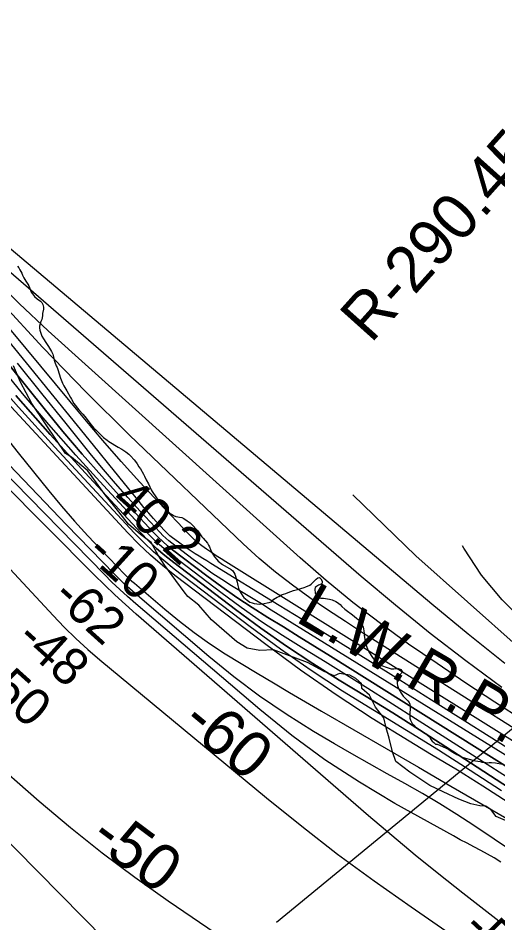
# Model space of a CAD drawing. Extents: x 3192986 to 3230865, y 867483 to 892886.
# Drawn here: x 3218620 to 3219484, y 874998 to 876628 of the extents above; entities that cross this region are included whole.
import ezdxf

# ---------------------------------------------------------------- set-up
doc = ezdxf.new("R2010")
doc.units = 0
for name, color, linetype in [('V-RIVR-EDGE', 7, 'Continuous'), ('V-RIVR-RANG', 7, 'Continuous'), ('V-RIVR-RANG-IDEN', 7, 'Continuous'), ('V-SITE-VEGE', 7, 'Continuous'), ('V-TOPO-DPTH', 7, 'Continuous'), ('V-TOPO-MAJR', 7, 'Continuous'), ('V-TOPO-MAJR-IDEN', 7, 'Continuous'), ('V-TOPO-MINR', 7, 'Continuous'), ('V-TOPO-MINR-IDEN', 7, 'Continuous'), ('V-TOPO-WATR', 7, 'Continuous'), ('V-TOPO-WATR-IDEN', 7, 'Continuous')]:
    doc.layers.add(name, color=color, linetype=linetype)

msp = doc.modelspace()

# ---------------------------------------------------------------- linework, layer by layer
at = {"layer": 'V-RIVR-EDGE'}
msp.add_lwpolyline([(3219498, 875182.3), (3219481.1, 875189.7), (3219471.6, 875202.3), (3219462.5, 875208), (3219451.6, 875208.5), (3219435.1, 875212), (3219413.8, 875220.7), (3219385.6, 875233.8), (3219361.3, 875245.2), (3219325.3, 875269.6), (3219300.5, 875288.4), (3219294.5, 875306.2), (3219288, 875330.6), (3219282.9, 875349.3), (3219278.5, 875367.1), (3219263.4, 875386.7), (3219252.6, 875408), (3219239.1, 875420.2), (3219238.7, 875428.9), (3219228.3, 875438.1), (3219217.4, 875443.8), (3219198.8, 875446.8), (3219189.2, 875443), (3219171, 875450.8), (3219141, 875467), (3219104.1, 875480.6), (3219080.2, 875489.7), (3219055.4, 875488.5), (3219032.8, 875492.9), (3219013.7, 875504.2), (3218968.6, 875543.9), (3218945.7, 875570.1), (3218925.7, 875585.7), (3218918.8, 875594.5), (3218904, 875614.5), (3218884.5, 875641.5), (3218872.4, 875660.2), (3218859.9, 875682.8), (3218840.3, 875697.7), (3218818.7, 875716), (3218801.3, 875738.2), (3218776.6, 875768.7), (3218745.9, 875812.2), (3218715.9, 875836.6), (3218705.1, 875843.2), (3218670.4, 875895), (3218644.9, 875933.3), (3218624.1, 875972.1), (3218612, 876001.6)], dxfattribs=at)
at = {"layer": 'V-RIVR-RANG'}
msp.add_line((3219857.7, 875633.4), (3219085.2, 874998.4), dxfattribs=at)
at = {"layer": 'V-SITE-VEGE'}
for points in [[(3218618.8, 876180.8), (3218621.2, 876177.8), (3218623.3, 876174.5), (3218626.6, 876168.1)], [(3218626.6, 876168.1), (3218628, 876164.6), (3218630.4, 876160.1), (3218634.1, 876153.8), (3218637.7, 876148.7), (3218639.3, 876145.2), (3218642.1, 876137.6), (3218643.7, 876134.3), (3218645.7, 876131.3), (3218649.8, 876126.4), (3218654.6, 876122), (3218660.5, 876117.9), (3218662.6, 876115.4), (3218664.5, 876112), (3218666, 876107.2), (3218665.6, 876103.6), (3218664, 876095.4), (3218663.7, 876091.7), (3218662.6, 876084.9), (3218661.1, 876081.2), (3218659.8, 876077.1), (3218658.8, 876073), (3218658.5, 876069.6), (3218659, 876065.8), (3218661.4, 876058.7), (3218663, 876055), (3218665.9, 876049.9), (3218669.9, 876043.5), (3218675, 876036.1), (3218680.2, 876027.4), (3218682.3, 876022.4), (3218683.6, 876017.8), (3218684.9, 876011.7), (3218685.9, 876008.1), (3218688.7, 876001.4), (3218690.4, 875998.6), (3218691.7, 875995), (3218693.9, 875987.1), (3218696.5, 875979.4), (3218700.1, 875970), (3218702.2, 875965.4), (3218707.9, 875956.1), (3218714.5, 875944.3), (3218715.9, 875941.4), (3218720.3, 875933.5), (3218722.5, 875930.5), (3218727, 875925.2), (3218729.5, 875922), (3218736.8, 875914.1), (3218740, 875910.3), (3218751.4, 875894.9), (3218756.7, 875889), (3218759.8, 875885.8), (3218773.7, 875872.4), (3218780.3, 875867.5), (3218783.6, 875865.3), (3218800.5, 875854.6), (3218806.7, 875851), (3218813.9, 875846.2), (3218819.4, 875842), (3218822.7, 875839), (3218829.1, 875831.9), (3218831.5, 875828.9), (3218834.3, 875824.8), (3218837.6, 875819.2), (3218840.2, 875815.5), (3218845.6, 875806.1), (3218847.9, 875802.7), (3218850.9, 875796.2), (3218854.6, 875788.5), (3218859.7, 875778.2), (3218861.5, 875775), (3218869.4, 875763.3), (3218878, 875751.8), (3218888.4, 875740.6), (3218893.7, 875735.6), (3218897.2, 875733.3), (3218899.9, 875731.7), (3218903.8, 875730.1), (3218907.7, 875729.2), (3218910.8, 875728.9), (3218914.9, 875727.9), (3218918.3, 875726.3), (3218924.7, 875722.2), (3218929.7, 875718.4), (3218932.2, 875716.3), (3218935.5, 875713.3), (3218940.1, 875707.9), (3218943.4, 875703.8), (3218951.1, 875693.4), (3218953.3, 875691), (3218961.1, 875681.7), (3218963.1, 875678.5), (3218964.9, 875675.3), (3218966.6, 875670.7), (3218969.7, 875663.8), (3218971.8, 875660.2), (3218974, 875657), (3218977.8, 875652.3), (3218980.5, 875649.4), (3218988, 875643.5)], [(3218988, 875643.5), (3219003.5, 875634.4), (3219006.5, 875632), (3219008.7, 875629.3), (3219010.5, 875626), (3219011.7, 875622.7), (3219014.5, 875611.5), (3219015.7, 875605.4), (3219016.8, 875600.6), (3219018.5, 875596.2), (3219021.9, 875591.1), (3219024.7, 875586.6), (3219026.6, 875584.1), (3219032.5, 875579), (3219037.6, 875575.6), (3219041.6, 875574.1), (3219045, 875573.2), (3219049.8, 875572.3), (3219055, 875572.2), (3219063.3, 875573.2), (3219068.8, 875574.3), (3219072.4, 875574.7), (3219075.5, 875575.9), (3219078.4, 875577.9), (3219080.8, 875580.8), (3219083.3, 875583), (3219086.6, 875584.6), (3219089.5, 875585.9), (3219094.3, 875588.6), (3219098.1, 875590.2), (3219102.1, 875591.3), (3219106.1, 875593.1), (3219116.1, 875596.9), (3219123, 875598.7), (3219135.3, 875602.1), (3219138.4, 875603.2), (3219145.2, 875606.3), (3219147.9, 875608.2), (3219150.4, 875610.3), (3219156.6, 875616.9), (3219159.6, 875619.4), (3219162.7, 875619.8), (3219165, 875617.6), (3219167.4, 875613.4), (3219167.8, 875609.9), (3219165.6, 875607.9), (3219161.2, 875606), (3219157.2, 875604), (3219154.7, 875602.3), (3219154.1, 875598.8), (3219154.8, 875591.5), (3219156.6, 875587.9), (3219158.8, 875585.5), (3219161.3, 875584), (3219165, 875583), (3219169.8, 875582.5), (3219177.4, 875581.5), (3219181, 875580.7), (3219185.6, 875579.5), (3219192.1, 875576.7), (3219195.1, 875575), (3219197.6, 875573.2), (3219199.9, 875571.1), (3219202.9, 875567.9), (3219208.2, 875563.2), (3219210.9, 875561), (3219222.5, 875552.5), (3219229.4, 875547), (3219232.5, 875544.4), (3219235.1, 875541.8), (3219237.4, 875538.7), (3219240.2, 875533.8), (3219241.4, 875530.6), (3219242.3, 875527.7), (3219242.8, 875524.1), (3219243, 875519.3), (3219243.3, 875516.1), (3219243.9, 875511.7), (3219245.4, 875503.2), (3219246.1, 875500.3), (3219247.4, 875496.3), (3219249.8, 875490), (3219251.7, 875486.1), (3219258.3, 875476.1), (3219262.3, 875470.6), (3219264.6, 875468), (3219268.6, 875465.1), (3219271.5, 875463.2), (3219274.2, 875461.7), (3219277.9, 875460.1), (3219281, 875459.2), (3219288.5, 875456.4), (3219292.1, 875455.6), (3219296.5, 875455.5), (3219304.8, 875456.1), (3219309.5, 875454.1), (3219311.7, 875450.5), (3219310.3, 875447.8), (3219308.2, 875445), (3219305.4, 875441.4), (3219303.4, 875437.4)], [(3219303.4, 875437.4), (3219302.7, 875433.9), (3219302.4, 875429.1), (3219303.2, 875425.2), (3219305.1, 875420.1), (3219307.2, 875416), (3219308.8, 875413.3), (3219313.7, 875406.2), (3219316.5, 875403.2), (3219322.1, 875397.8), (3219324, 875395.1), (3219325.6, 875391.6), (3219325.8, 875388.2), (3219325.8, 875383.7), (3219325.3, 875375.9), (3219325.2, 875366.7), (3219326.4, 875363), (3219328.2, 875359.5), (3219329.9, 875356.9), (3219332.5, 875353.7), (3219335.7, 875350.6), (3219353.9, 875338.9), (3219356.9, 875336.5), (3219360, 875333.6), (3219362, 875331.1), (3219363.4, 875328.1), (3219365.9, 875325.2), (3219368.5, 875322.6), (3219371.7, 875319.8), (3219374.8, 875319.6), (3219389.9, 875313.4), (3219396, 875309.9), (3219399.9, 875307.4), (3219402.9, 875305.2), (3219409.9, 875301.2), (3219416.7, 875297.9), (3219420, 875296.6), (3219432.4, 875292.7), (3219439.2, 875290.9), (3219443.9, 875289.7), (3219448, 875288.9), (3219452, 875288.4), (3219455.4, 875287.6), (3219459, 875287.1), (3219462.1, 875286.5), (3219465.3, 875286.2), (3219468.5, 875286.7), (3219472.8, 875287), (3219480, 875286.1), (3219492.1, 875283.9)]]:
    msp.add_lwpolyline(points, dxfattribs=at)
at = {"layer": 'V-TOPO-DPTH'}
for points in [[(3219692, 875192.4), (3219364.3, 875399.1), (3219296, 875442), (3219227.5, 875484.8), (3219159, 875527.3), (3219090.4, 875569.7), (3218967.2, 875645.4), (3218960, 875649.8), (3218952.9, 875654.2), (3218945.8, 875658.6), (3218938.6, 875662.9), (3218931.5, 875667.4), (3218924.6, 875672), (3218917.7, 875676.8), (3218911, 875681.8), (3218895.7, 875693.4), (3218893.5, 875695.2), (3218891.4, 875697), (3218889.3, 875699), (3218887.3, 875701), (3218873.1, 875716.4), (3218864.1, 875726.3), (3218855.3, 875736.2), (3218846.7, 875746.4), (3218838.2, 875756.7), (3218819.3, 875780), (3218801.5, 875802), (3218783.6, 875824), (3218765.8, 875846), (3218747.9, 875868), (3218395.4, 876300.2)], [(3218519.2, 876107.9), (3218666.7, 875924.7), (3218700.8, 875883.3), (3218735.4, 875842.4), (3218770.8, 875802.3), (3218806.8, 875762.6), (3218864.1, 875700.8), (3218872.1, 875692.7), (3218880.4, 875684.8), (3218889, 875677.3), (3218897.9, 875670.1), (3218960, 875622.9), (3218986.8, 875603.3), (3219013.9, 875584.1), (3219041.6, 875565.9), (3219069.7, 875548.2), (3219098.1, 875530.9), (3219126.4, 875513.4), (3219154.6, 875495.9), (3219182.8, 875478.3), (3219639.8, 875191)], [(3218519.2, 876107.9), (3218666.7, 875924.7), (3218700.8, 875883.3), (3218735.4, 875842.4), (3218770.8, 875802.3), (3218806.8, 875762.6), (3218864.1, 875700.8), (3218872.1, 875692.7), (3218880.4, 875684.8), (3218889, 875677.3), (3218897.9, 875670.1), (3218960, 875622.9), (3218986.8, 875603.3), (3219013.9, 875584.1), (3219041.6, 875565.9), (3219069.7, 875548.2), (3219098.1, 875530.9), (3219126.4, 875513.4), (3219154.6, 875495.9), (3219182.8, 875478.3), (3219639.8, 875191)], [(3218615.7, 875947.8), (3218677.9, 875877.8), (3218740.9, 875808.6), (3218840.9, 875700.7), (3218854.9, 875686.3), (3218869.4, 875672.5), (3218884.5, 875659.4), (3218900.2, 875646.9), (3219011.4, 875562.3), (3219057, 875528.8), (3219103.2, 875496.3), (3219150.6, 875465.3), (3219198.5, 875435.3), (3219246.9, 875405.8), (3219295, 875376), (3219342.9, 875345.7), (3219390.5, 875315.1), (3219618, 875167.4)], [(3219618, 875167.4), (3219390.5, 875315.1), (3219342.9, 875345.7), (3219295, 875376), (3219246.9, 875405.8), (3219198.5, 875435.3), (3219150.6, 875465.3), (3219103.2, 875496.3), (3219057, 875528.8), (3219011.4, 875562.3), (3218900.2, 875646.9), (3218884.5, 875659.4), (3218869.4, 875672.5), (3218854.9, 875686.3), (3218840.9, 875700.7), (3218740.9, 875808.6), (3218677.9, 875877.8), (3218615.7, 875947.8)], [(3219502.8, 875214.5), (3219457.2, 875244), (3219411.1, 875272.7), (3219364.7, 875300.8), (3219324.1, 875325), (3219257.8, 875366), (3219192.6, 875408.5), (3219128.8, 875453.1), (3219066, 875499.2), (3218902.4, 875623.6), (3218880, 875641.5), (3218858.4, 875660.2), (3218837.7, 875680), (3218817.7, 875700.5), (3218599.5, 875936)], [(3219502.8, 875214.5), (3219457.2, 875244), (3219411.1, 875272.7), (3219364.7, 875300.8), (3219324.1, 875325), (3219257.8, 875366), (3219192.6, 875408.5), (3219128.8, 875453.1), (3219066, 875499.2), (3218902.4, 875623.6), (3218880, 875641.5), (3218858.4, 875660.2), (3218837.7, 875680), (3218817.7, 875700.5), (3218599.5, 875936)], [(3218579.3, 875895.9), (3218620.3, 875844.9), (3218675.5, 875776.3), (3218698.3, 875748.7), (3218721.6, 875721.6), (3218745.7, 875695.1), (3218770.2, 875669), (3218811.6, 875626.3), (3218815.9, 875622), (3218820.3, 875617.8), (3218824.8, 875613.7), (3218829.4, 875609.6), (3218884.3, 875562.7), (3218910.4, 875541.4), (3218937.2, 875520.8), (3218964.8, 875501.4), (3218993, 875482.8), (3219021.8, 875465), (3219050.7, 875447.4), (3219079.7, 875430.1), (3219108.9, 875412.9), (3219166.6, 875379.3), (3219224.8, 875345.6), (3219282.9, 875311.8), (3219341.1, 875278.1), (3219399.2, 875244.3), (3219601.2, 875127.3)], [(3218579.3, 875895.9), (3218620.3, 875844.9), (3218675.5, 875776.3), (3218698.3, 875748.7), (3218721.6, 875721.6), (3218745.7, 875695.1), (3218770.2, 875669), (3218811.6, 875626.3), (3218815.9, 875622), (3218820.3, 875617.8), (3218824.8, 875613.7), (3218829.4, 875609.6), (3218884.3, 875562.7), (3218910.4, 875541.4), (3218937.2, 875520.8), (3218964.8, 875501.4), (3218993, 875482.8), (3219021.8, 875465), (3219050.7, 875447.4), (3219079.7, 875430.1), (3219108.9, 875412.9), (3219166.6, 875379.3), (3219224.8, 875345.6), (3219282.9, 875311.8), (3219341.1, 875278.1), (3219399.2, 875244.3), (3219601.2, 875127.3)], [(3219548.9, 875100.3), (3219440.7, 875173.3), (3219410.2, 875193.2), (3219379.4, 875212.5), (3219348, 875230.9), (3219316.3, 875248.8), (3219284.4, 875266.3), (3219252.6, 875284.1), (3219221, 875302.3), (3219189.6, 875320.6), (3219152.1, 875342.8), (3219102.9, 875373.7), (3219054.9, 875406.1), (3219008.6, 875441.1), (3218963.5, 875477.6), (3218830.6, 875591.2), (3218821.1, 875599.6), (3218811.7, 875608.2), (3218802.6, 875617), (3218793.6, 875626), (3218707.3, 875715.1), (3218655.5, 875768.9), (3218603.9, 875823)], [(3219548.9, 875100.3), (3219440.7, 875173.3), (3219410.2, 875193.2), (3219379.4, 875212.5), (3219348, 875230.9), (3219316.3, 875248.8), (3219284.4, 875266.3), (3219252.6, 875284.1), (3219221, 875302.3), (3219189.6, 875320.6), (3219152.1, 875342.8), (3219102.9, 875373.7), (3219054.9, 875406.1), (3219008.6, 875441.1), (3218963.5, 875477.6), (3218830.6, 875591.2), (3218821.1, 875599.6), (3218811.7, 875608.2), (3218802.6, 875617), (3218793.6, 875626), (3218707.3, 875715.1), (3218655.5, 875768.9), (3218603.9, 875823)], [(3218494.5, 875253), (3219097.1, 874642)], [(3218494.5, 875253), (3219097.1, 874642)]]:
    msp.add_lwpolyline(points, dxfattribs=at)
at = {"layer": 'V-TOPO-MAJR'}
for points in [[(3219530.7, 875361.7), (3219478.3, 875395.6), (3219426.2, 875429.9), (3219374.5, 875464.9), (3219323.1, 875500.2), (3219272.6, 875536.9), (3219223.1, 875574.7), (3219175.1, 875614.4), (3219128, 875655.3), (3218674.1, 876064.7), (3218621.8, 876113.6), (3218570.7, 876163.8), (3218521.5, 876215.8), (3218473.6, 876269), (3218398, 876356.1), (3218388.9, 876366.8), (3218380, 876377.5), (3218371.3, 876388.5), (3218362.7, 876399.6), (3217944.5, 877172.1)], [(3219489.1, 875107.4), (3219477.5, 875114.9), (3219465.5, 875121.8), (3219453.3, 875128.4), (3219440.9, 875134.7), (3219428.7, 875141.1), (3219416.4, 875147.7), (3219404.3, 875154.4), (3219298.4, 875213.1), (3219234.6, 875251.1), (3219172.5, 875291.5), (3219113, 875335.5), (3219055.2, 875382), (3218831.8, 875572.8), (3218817.3, 875585.5), (3218803.1, 875598.5), (3218789.1, 875611.9), (3218775.4, 875625.5), (3218586.8, 875818)], [(3218563, 875300), (3218658.1, 875217), (3218714.2, 875169.8), (3218771.4, 875123.9), (3218830.2, 875080.2), (3218890, 875037.8), (3219046.3, 874931.4)]]:
    msp.add_lwpolyline(points, dxfattribs=at)
at = {"layer": 'V-TOPO-MINR'}
for points in [[(3219496.3, 875465.3), (3219430.3, 875518.1), (3219365, 875571.9), (3218431.3, 876359.2), (3218425, 876364.7), (3218418.9, 876370.4), (3218413.1, 876376.4), (3218407.4, 876382.6), (3218398.7, 876392.5), (3218397.6, 876393.8), (3218395.4, 876396.5), (3218394.3, 876397.9), (3218389.6, 876404.2), (3218388.7, 876405.4), (3218387.1, 876407.8), (3218385.6, 876410.4), (3218383.8, 876414.4), (3218382.6, 876417.2), (3218381.1, 876420.8), (3218380.2, 876422.6), (3218377, 876429.6), (3218374.5, 876434.9), (3217976.5, 877200.8)], [(3219685.8, 875239.4), (3219274.5, 875498.7), (3219241.9, 875519.4), (3219209.5, 875540.5), (3219177.3, 875561.8), (3219145.2, 875583.4), (3219113.9, 875606), (3219083.4, 875629.5), (3219054.1, 875654.5), (3219025.6, 875680.5), (3218820.9, 875876.7), (3218741.8, 875954.7), (3218664.4, 876034.3), (3218589.3, 876116.1), (3218515.8, 876199.4), (3218397.4, 876337.7), (3218384.5, 876353.1), (3218371.7, 876368.7), (3217935.9, 877173.1)], [(3219491.2, 875422), (3219426.3, 875470), (3219362.3, 875519.2), (3219299.6, 875570), (3219237.9, 875622), (3218548.3, 876219.2), (3218519.6, 876245.1), (3218491.7, 876271.7), (3218465, 876299.5), (3218438.9, 876328), (3218398.4, 876374.3), (3218393.3, 876380.3), (3218388.2, 876386.4), (3218383.3, 876392.5), (3218378.5, 876398.8), (3217958.1, 877170.4)], [(3219689.1, 875214.1), (3218994.4, 875648.1), (3218985.5, 875653.7), (3218976.8, 875659.3), (3218968.1, 875665), (3218959.4, 875670.8), (3218951, 875676.9), (3218942.8, 875683.3), (3218935.2, 875690.2), (3218927.8, 875697.5), (3218873.3, 875755.3), (3218839.2, 875792), (3218805.7, 875829.2), (3218772.8, 875867), (3218740.4, 875905.2), (3218396.4, 876319), (3218379.8, 876339.3), (3218363.3, 876359.8), (3218347.2, 876380.5), (3218331.2, 876401.3), (3217981.5, 877075)], [(3219490.6, 875235.6), (3219434, 875272.5), (3219377, 875308.9), (3219319.6, 875344.6), (3219261.8, 875379.7), (3219204.5, 875415.5), (3219147.9, 875452.4), (3219092.6, 875491.2), (3219038.2, 875531.2), (3218901.3, 875635.2), (3218882.3, 875650.5), (3218863.9, 875666.3), (3218846.3, 875683.1), (3218829.3, 875700.6), (3218686.2, 875855), (3218620.6, 875927), (3218555.7, 875999.6), (3218492, 876073.2), (3218429, 876147.4), (3218343.8, 876249.5), (3218324, 876273.2), (3218304.2, 876296.9), (3217857.3, 876973.3)], [(3219692, 875192.4), (3219364.3, 875399.1), (3219296, 875442), (3219227.5, 875484.8), (3219159, 875527.3), (3219090.4, 875569.7), (3218967.2, 875645.4), (3218960, 875649.8), (3218952.9, 875654.2), (3218945.8, 875658.6), (3218938.6, 875662.9), (3218931.5, 875667.4), (3218924.6, 875672), (3218917.7, 875676.8), (3218911, 875681.8), (3218895.7, 875693.4), (3218893.5, 875695.2), (3218891.4, 875697), (3218889.3, 875699), (3218887.3, 875701), (3218873.1, 875716.4), (3218864.1, 875726.3), (3218855.3, 875736.2), (3218846.7, 875746.4), (3218838.2, 875756.7), (3218819.3, 875780), (3218801.5, 875802), (3218783.6, 875824), (3218765.8, 875846), (3218747.9, 875868), (3218395.4, 876300.2)], [(3218111.8, 876246), (3218112.2, 876241.3), (3218147.6, 876183.6), (3218157.7, 876167.6), (3218168.2, 876151.7), (3218179.1, 876136.1), (3218190.4, 876120.8), (3218257.5, 876031.8), (3218303.3, 875972.9), (3218350.4, 875914.9), (3218399.2, 875858.5), (3218449.2, 875803), (3218682.9, 875551.5), (3218703.1, 875530.5), (3218723.9, 875510.1), (3218745.4, 875490.6), (3218767.5, 875471.5), (3219067.5, 875222.9), (3219131, 875171.8), (3219195.3, 875121.8), (3219261, 875073.5), (3219327.6, 875026.5), (3219429.2, 874956.7)], [(3219485.6, 875000.8), (3219420.7, 875051.4), (3219377.7, 875085.5), (3219335, 875120), (3219292.9, 875155.2), (3219251.2, 875190.9), (3218832.8, 875554.1), (3218813.4, 875571.3), (3218794.3, 875588.8), (3218775.6, 875606.6), (3218757.1, 875624.8), (3218334.4, 876050.2)], [(3219615.3, 875187), (3219287.8, 875396.1), (3219249.6, 875420.3), (3219211.4, 875444.2), (3219173, 875467.9), (3219134.5, 875491.5), (3219096.2, 875515.4), (3219058.6, 875540.2), (3219021.7, 875566.2), (3218985.4, 875592.9), (3218899.1, 875658.5), (3218886.8, 875668.4), (3218874.9, 875678.6), (3218863.5, 875689.5), (3218852.5, 875700.7), (3218773.7, 875785.7), (3218724.2, 875840.2), (3218675.5, 875895.4), (3218627.9, 875951.7), (3218581, 876008.5)], [(3219684.9, 875184.3), (3219075.9, 875561.4), (3219058.1, 875572.4), (3219040.2, 875583.4), (3219022.3, 875594.4), (3219004.4, 875605.3), (3218986.7, 875616.5), (3218969.2, 875628.1), (3218952.1, 875640.2), (3218935.2, 875652.6), (3218896.8, 875681.8), (3218891.3, 875686.2), (3218885.9, 875690.9), (3218880.7, 875695.8), (3218875.7, 875700.9), (3218839.9, 875739.5), (3218817.5, 875764.3), (3218795.3, 875789.3), (3218773.7, 875814.8), (3218752.4, 875840.6), (3218706.7, 875897.3), (3218662.7, 875951.7), (3218618.7, 876006)], [(3219618, 875167.4), (3219390.5, 875315.1), (3219342.9, 875345.7), (3219295, 875376), (3219246.9, 875405.8), (3219198.5, 875435.3), (3219150.6, 875465.3), (3219103.2, 875496.3), (3219057, 875528.8), (3219011.4, 875562.3), (3218900.2, 875646.9), (3218884.5, 875659.4), (3218869.4, 875672.5), (3218854.9, 875686.3), (3218840.9, 875700.7), (3218740.9, 875808.6), (3218677.9, 875877.8), (3218615.7, 875947.8)], [(3219502.8, 875214.5), (3219457.2, 875244), (3219411.1, 875272.7), (3219364.7, 875300.8), (3219324.1, 875325), (3219257.8, 875366), (3219192.6, 875408.5), (3219128.8, 875453.1), (3219066, 875499.2), (3218902.4, 875623.6), (3218880, 875641.5), (3218858.4, 875660.2), (3218837.7, 875680), (3218817.7, 875700.5), (3218599.5, 875936)], [(3218579.3, 875895.9), (3218620.3, 875844.9), (3218675.5, 875776.3), (3218698.3, 875748.7), (3218721.6, 875721.6), (3218745.7, 875695.1), (3218770.2, 875669), (3218811.6, 875626.3), (3218815.9, 875622), (3218820.3, 875617.8), (3218824.8, 875613.7), (3218829.4, 875609.6), (3218884.3, 875562.7), (3218910.4, 875541.4), (3218937.2, 875520.8), (3218964.8, 875501.4), (3218993, 875482.8), (3219021.8, 875465), (3219050.7, 875447.4), (3219079.7, 875430.1), (3219108.9, 875412.9), (3219166.6, 875379.3), (3219224.8, 875345.6), (3219282.9, 875311.8), (3219341.1, 875278.1), (3219399.2, 875244.3), (3219601.2, 875127.3)], [(3219548.9, 875100.3), (3219440.7, 875173.3), (3219410.2, 875193.2), (3219379.4, 875212.5), (3219348, 875230.9), (3219316.3, 875248.8), (3219284.4, 875266.3), (3219252.6, 875284.1), (3219221, 875302.3), (3219189.6, 875320.6), (3219152.1, 875342.8), (3219102.9, 875373.7), (3219054.9, 875406.1), (3219008.6, 875441.1), (3218963.5, 875477.6), (3218830.6, 875591.2), (3218821.1, 875599.6), (3218811.7, 875608.2), (3218802.6, 875617), (3218793.6, 875626), (3218707.3, 875715.1), (3218655.5, 875768.9), (3218603.9, 875823)], [(3219608, 875420.6), (3219564.7, 875456.5), (3219522.1, 875493.4), (3219336.1, 875659), (3219223, 875768.9)], [(3219808.9, 875307.9), (3219796.7, 875316.6), (3219784.5, 875325.4), (3219762.8, 875341.1), (3219740.1, 875358.1), (3219717.7, 875375.6), (3219695.9, 875393.7), (3219674.4, 875412.2), (3219532.7, 875538.4), (3219491.6, 875579.9), (3219454.3, 875624.1), (3219422.8, 875672.7), (3219420.2, 875677.3)], [(3218494.5, 875253), (3219097.1, 874642)]]:
    msp.add_lwpolyline(points, dxfattribs=at)
at = {"layer": 'V-TOPO-WATR'}
msp.add_lwpolyline([(3219639.8, 875191), (3219182.8, 875478.3), (3219154.6, 875495.9), (3219126.4, 875513.4), (3219098.1, 875530.9), (3219069.7, 875548.2), (3219041.6, 875565.9), (3219013.9, 875584.1), (3218986.8, 875603.3), (3218960, 875622.9), (3218897.9, 875670.1), (3218889, 875677.3), (3218880.4, 875684.8), (3218872.1, 875692.7), (3218864.1, 875700.8), (3218806.8, 875762.6), (3218770.8, 875802.3), (3218735.4, 875842.4), (3218700.8, 875883.3), (3218666.7, 875924.7), (3218519.2, 876107.9)], dxfattribs=at)

# ---------------------------------------------------------------- texts
at = {"layer": 'V-RIVR-RANG'}
for s, rotation, p in [('40.2', 317.9783, (3218784.4, 875755.7)), ('-10', 317.9122, (3218740, 875661.2)), ('-62', 317.9122, (3218678.9, 875581.6)), ('-48', 317.9122, (3218613.7, 875505.7)), ('-50', 317.9122, (3218545.2, 875432.9)), ('-51', 317.1344, (3219417.6, 874984))]:
    msp.add_text(s, height=67, rotation=rotation, dxfattribs=at).set_placement(p)
at = {"layer": 'V-RIVR-RANG-IDEN'}
msp.add_text('R-290.45', height=83, rotation=48.1218, dxfattribs=at).set_placement((3219255.5, 876040.4))
at = {"layer": 'V-TOPO-MAJR-IDEN'}
msp.add_text('-50', height=83, rotation=323.3432, dxfattribs=at).set_placement((3218745.3, 875143.3))
at = {"layer": 'V-TOPO-MINR-IDEN'}
msp.add_text('-60', height=83, rotation=320.3552, dxfattribs=at).set_placement((3218910.7, 875352.9))
at = {"layer": 'V-TOPO-WATR-IDEN'}
msp.add_text('L.W.R.P.', height=83, rotation=329.7072, dxfattribs=at).set_placement((3219117.3, 875542.2))

doc.saveas('drawing.dxf')
